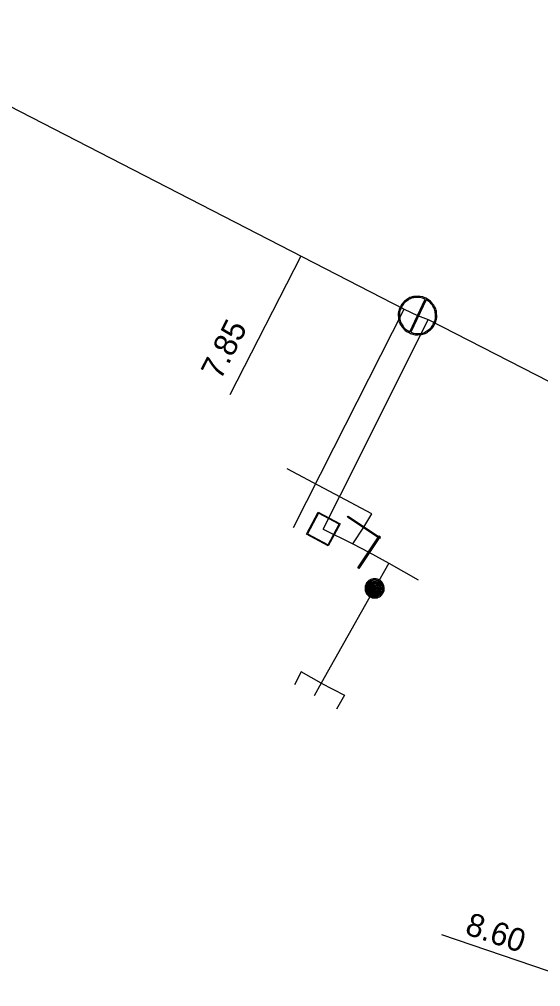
# Model space of a CAD drawing. Extents: x -820257 to -819974, y -1070894 to -1070484.
# Drawn here: x -820052 to -820024.9, y -1070627.8 to -1070577.4 of the extents above; entities that cross this region are included whole.
import ezdxf

# ---------------------------------------------------------------- set-up
doc = ezdxf.new("R2010")
doc.units = 0
for name, color, linetype in [('Oměrka vodovodu', 7, 'Continuous'), ('Oměrka-text', 7, 'Continuous'), ('Pás-šoupě', 7, 'Continuous'), ('Přípojka vodovodu', 7, 'Continuous'), ('Přípojkový uzávěr', 7, 'Continuous'), ('Roz-řad', 7, 'Continuous'), ('Řad-šoupě', 7, 'Continuous'), ('Šachta vodovodní', 7, 'Continuous')]:
    doc.layers.add(name, color=color, linetype=linetype)

msp = doc.modelspace()

# ---------------------------------------------------------------- linework, layer by layer
at = {"layer": 'Oměrka vodovodu'}
for p, q in [((-820037.366, -1070589.716), (-820041.064, -1070596.946)), ((-820030.03, -1070625.09), (-820022.07, -1070627.805))]:
    msp.add_line(p, q, dxfattribs=at)
at = {"layer": 'Pás-šoupě'}
for points in [[(-820031.687, -1070593.665), (-820030.887, -1070591.969)], [(-820030.831, -1070591.997), (-820031.629, -1070593.689)]]:
    msp.add_lwpolyline(points, dxfattribs=at)
for points in [[(-820030.859, -1070591.913), (-820030.631, -1070592.02), (-820030.47, -1070592.239), (-820030.308, -1070592.458), (-820030.289, -1070592.733), (-820030.269, -1070593.008), (-820030.381, -1070593.245), (-820030.492, -1070593.48), (-820030.712, -1070593.639), (-820030.933, -1070593.798), (-820031.205, -1070593.815), (-820031.477, -1070593.833), (-820031.712, -1070593.722), (-820031.946, -1070593.611), (-820032.106, -1070593.39), (-820032.265, -1070593.169), (-820032.283, -1070592.898), (-820032.3, -1070592.627), (-820032.19, -1070592.392), (-820032.078, -1070592.155), (-820031.854, -1070591.995), (-820031.63, -1070591.834), (-820031.359, -1070591.82), (-820031.088, -1070591.805), (-820030.859, -1070591.913)], [(-820030.887, -1070591.969), (-820031.099, -1070591.868), (-820031.354, -1070591.882), (-820031.609, -1070591.896), (-820031.819, -1070592.046), (-820032.028, -1070592.196), (-820032.133, -1070592.418), (-820032.237, -1070592.639), (-820032.22, -1070592.893), (-820032.203, -1070593.147), (-820032.054, -1070593.354), (-820031.906, -1070593.561), (-820031.687, -1070593.665)], [(-820031.629, -1070593.689), (-820031.432, -1070593.768), (-820031.209, -1070593.753), (-820030.955, -1070593.736), (-820030.748, -1070593.587), (-820030.542, -1070593.439), (-820030.437, -1070593.218), (-820030.332, -1070592.996), (-820030.352, -1070592.738), (-820030.371, -1070592.48), (-820030.521, -1070592.275), (-820030.652, -1070592.097), (-820030.831, -1070591.997)]]:
    msp.add_open_spline(points, degree=3, dxfattribs=at)
at = {"layer": 'Přípojka vodovodu'}
msp.add_line((-820036.301, -1070611.976), (-820036.676, -1070612.643), dxfattribs=at)
for points in [[(-820032.786, -1070605.734), (-820033.522, -1070607.041), (-820036.301, -1070611.976)], [(-820036.301, -1070611.976), (-820037.352, -1070611.398), (-820037.704, -1070612.064)], [(-820036.301, -1070611.976), (-820035.087, -1070612.605), (-820035.502, -1070613.335)]]:
    msp.add_lwpolyline(points, dxfattribs=at)
at = {"layer": 'Přípojkový uzávěr'}
for points in [[(-820033.522, -1070606.541), (-820033.396, -1070606.541), (-820033.277, -1070606.606), (-820033.157, -1070606.67), (-820033.089, -1070606.791), (-820033.022, -1070606.911), (-820033.022, -1070607.042), (-820033.022, -1070607.172), (-820033.088, -1070607.291), (-820033.154, -1070607.409), (-820033.273, -1070607.475), (-820033.392, -1070607.541), (-820033.522, -1070607.541), (-820033.652, -1070607.541), (-820033.771, -1070607.475), (-820033.89, -1070607.409), (-820033.956, -1070607.291), (-820034.022, -1070607.172), (-820034.022, -1070607.042), (-820034.022, -1070606.911), (-820033.955, -1070606.791), (-820033.888, -1070606.67), (-820033.768, -1070606.606), (-820033.649, -1070606.541), (-820033.522, -1070606.541)], [(-820033.522, -1070606.588), (-820033.637, -1070606.588), (-820033.745, -1070606.647), (-820033.853, -1070606.705), (-820033.914, -1070606.814), (-820033.975, -1070606.923), (-820033.975, -1070607.042), (-820033.975, -1070607.159), (-820033.915, -1070607.267), (-820033.856, -1070607.375), (-820033.748, -1070607.435), (-820033.639, -1070607.494), (-820033.522, -1070607.494), (-820033.404, -1070607.494), (-820033.296, -1070607.435), (-820033.188, -1070607.375), (-820033.128, -1070607.267), (-820033.069, -1070607.159), (-820033.069, -1070607.042), (-820033.069, -1070606.923), (-820033.13, -1070606.814), (-820033.192, -1070606.705), (-820033.3, -1070606.647), (-820033.408, -1070606.588), (-820033.522, -1070606.588)], [(-820033.522, -1070606.622), (-820033.416, -1070606.622), (-820033.317, -1070606.676), (-820033.217, -1070606.73), (-820033.16, -1070606.831), (-820033.103, -1070606.932), (-820033.103, -1070607.042), (-820033.103, -1070607.151), (-820033.158, -1070607.25), (-820033.213, -1070607.35), (-820033.313, -1070607.405), (-820033.413, -1070607.46), (-820033.522, -1070607.46), (-820033.631, -1070607.46), (-820033.731, -1070607.405), (-820033.831, -1070607.35), (-820033.886, -1070607.25), (-820033.941, -1070607.151), (-820033.941, -1070607.042), (-820033.941, -1070606.932), (-820033.885, -1070606.831), (-820033.828, -1070606.73), (-820033.728, -1070606.676), (-820033.628, -1070606.622), (-820033.522, -1070606.622)], [(-820033.523, -1070606.666), (-820033.679, -1070606.666), (-820033.788, -1070606.776), (-820033.897, -1070606.886), (-820033.897, -1070607.042), (-820033.897, -1070607.197), (-820033.787, -1070607.307), (-820033.677, -1070607.416), (-820033.523, -1070607.416), (-820033.367, -1070607.416), (-820033.257, -1070607.307), (-820033.147, -1070607.197), (-820033.147, -1070607.042), (-820033.147, -1070606.886), (-820033.256, -1070606.776), (-820033.365, -1070606.666), (-820033.523, -1070606.666)], [(-820033.523, -1070606.712), (-820033.386, -1070606.712), (-820033.29, -1070606.808), (-820033.195, -1070606.904), (-820033.195, -1070607.04), (-820033.195, -1070607.177), (-820033.291, -1070607.272), (-820033.387, -1070607.368), (-820033.523, -1070607.368), (-820033.66, -1070607.368), (-820033.755, -1070607.272), (-820033.851, -1070607.177), (-820033.851, -1070607.04), (-820033.851, -1070606.904), (-820033.755, -1070606.808), (-820033.66, -1070606.712), (-820033.523, -1070606.712)], [(-820033.523, -1070606.752), (-820033.643, -1070606.752), (-820033.727, -1070606.836), (-820033.811, -1070606.921), (-820033.811, -1070607.04), (-820033.811, -1070607.16), (-820033.727, -1070607.244), (-820033.643, -1070607.329), (-820033.523, -1070607.329), (-820033.403, -1070607.329), (-820033.319, -1070607.244), (-820033.234, -1070607.16), (-820033.234, -1070607.04), (-820033.234, -1070606.921), (-820033.318, -1070606.836), (-820033.402, -1070606.752), (-820033.523, -1070606.752)], [(-820033.522, -1070606.791), (-820033.417, -1070606.791), (-820033.345, -1070606.865), (-820033.272, -1070606.938), (-820033.272, -1070607.042), (-820033.272, -1070607.145), (-820033.345, -1070607.218), (-820033.418, -1070607.291), (-820033.522, -1070607.291), (-820033.625, -1070607.291), (-820033.699, -1070607.218), (-820033.772, -1070607.145), (-820033.772, -1070607.042), (-820033.772, -1070606.938), (-820033.699, -1070606.865), (-820033.627, -1070606.791), (-820033.522, -1070606.791)], [(-820033.522, -1070606.838), (-820033.607, -1070606.838), (-820033.666, -1070606.897), (-820033.725, -1070606.956), (-820033.725, -1070607.041), (-820033.725, -1070607.125), (-820033.666, -1070607.185), (-820033.607, -1070607.244), (-820033.522, -1070607.244), (-820033.438, -1070607.244), (-820033.379, -1070607.185), (-820033.319, -1070607.125), (-820033.319, -1070607.041), (-820033.319, -1070606.956), (-820033.379, -1070606.897), (-820033.438, -1070606.838), (-820033.522, -1070606.838)], [(-820033.522, -1070606.872), (-820033.452, -1070606.872), (-820033.403, -1070606.921), (-820033.354, -1070606.97), (-820033.354, -1070607.041), (-820033.354, -1070607.111), (-820033.403, -1070607.16), (-820033.452, -1070607.209), (-820033.522, -1070607.209), (-820033.593, -1070607.209), (-820033.642, -1070607.16), (-820033.691, -1070607.111), (-820033.691, -1070607.041), (-820033.691, -1070606.97), (-820033.642, -1070606.921), (-820033.593, -1070606.872), (-820033.522, -1070606.872)], [(-820033.522, -1070606.916), (-820033.574, -1070606.916), (-820033.61, -1070606.953), (-820033.647, -1070606.99), (-820033.647, -1070607.041), (-820033.647, -1070607.093), (-820033.61, -1070607.13), (-820033.574, -1070607.166), (-820033.522, -1070607.166), (-820033.47, -1070607.166), (-820033.433, -1070607.13), (-820033.397, -1070607.093), (-820033.397, -1070607.041), (-820033.397, -1070606.99), (-820033.433, -1070606.953), (-820033.47, -1070606.916), (-820033.522, -1070606.916)], [(-820033.522, -1070606.963), (-820033.489, -1070606.963), (-820033.467, -1070606.986), (-820033.444, -1070607.008), (-820033.444, -1070607.041), (-820033.444, -1070607.074), (-820033.467, -1070607.096), (-820033.489, -1070607.119), (-820033.522, -1070607.119), (-820033.555, -1070607.119), (-820033.577, -1070607.096), (-820033.6, -1070607.074), (-820033.6, -1070607.041), (-820033.6, -1070607.008), (-820033.577, -1070606.986), (-820033.555, -1070606.963), (-820033.522, -1070606.963)], [(-820033.522, -1070606.994), (-820033.542, -1070606.994), (-820033.556, -1070607.008), (-820033.569, -1070607.021), (-820033.569, -1070607.041), (-820033.569, -1070607.061), (-820033.556, -1070607.075), (-820033.542, -1070607.088), (-820033.522, -1070607.088), (-820033.502, -1070607.088), (-820033.489, -1070607.075), (-820033.475, -1070607.061), (-820033.475, -1070607.041), (-820033.475, -1070607.021), (-820033.489, -1070607.008), (-820033.502, -1070606.994), (-820033.522, -1070606.994)]]:
    msp.add_open_spline(points, degree=3, dxfattribs=at)
at = {"layer": 'Roz-řad'}
for p, q in [((-820110.178, -1070552.224), (-820031.976, -1070592.492)), ((-820035.657, -1070599.724), (-820031.976, -1070592.492)), ((-820031.976, -1070592.492), (-820031.285, -1070592.818)), ((-820034.405, -1070600.368), (-820030.723, -1070593.018)), ((-820031.285, -1070592.818), (-820030.723, -1070593.018)), ((-820030.723, -1070593.018), (-819996.078, -1070610.817)), ((-820037.753, -1070603.867), (-820035.657, -1070599.724)), ((-820036.199, -1070603.948), (-820034.405, -1070600.368)), ((-820036.199, -1070603.948), (-820034.663, -1070604.726)), ((-820034.663, -1070604.726), (-820034.083, -1070603.855)), ((-820034.663, -1070604.726), (-820033.818, -1070605.153))]:
    msp.add_line(p, q, dxfattribs=at)
for points in [[(-820034.083, -1070603.855), (-820033.669, -1070603.154), (-820038.09, -1070600.814)], [(-820033.818, -1070605.153), (-820032.786, -1070605.734), (-820031.245, -1070606.602)]]:
    msp.add_lwpolyline(points, dxfattribs=at)
at = {"layer": 'Řad-šoupě'}
for points in [[(-820034.897, -1070603.274), (-820033.233, -1070604.382), (-820033.267, -1070604.434), (-820034.932, -1070603.326), (-820034.897, -1070603.274)], [(-820034.397, -1070605.967), (-820033.289, -1070604.303), (-820033.237, -1070604.337), (-820034.345, -1070606.002), (-820034.397, -1070605.967)]]:
    msp.add_lwpolyline(points, dxfattribs=at)
at = {"layer": 'Šachta vodovodní'}
for points in [[(-820036.46, -1070603.066), (-820035.317, -1070603.685), (-820035.936, -1070604.828), (-820037.079, -1070604.209), (-820036.46, -1070603.066)], [(-820037.024, -1070604.193), (-820035.953, -1070604.773), (-820035.372, -1070603.702), (-820036.444, -1070603.121), (-820037.024, -1070604.193)]]:
    msp.add_lwpolyline(points, dxfattribs=at)

# ---------------------------------------------------------------- texts
at = {"layer": 'Oměrka-text'}
for s, rotation, p in [(' 7.85', 62.9112, (-820041.763, -1070596.62)), (' 8.60', 341.1665, (-820029.289, -1070624.9))]:
    msp.add_text(s, height=1.2, rotation=rotation, dxfattribs=at).set_placement(p)

doc.saveas('drawing.dxf')
